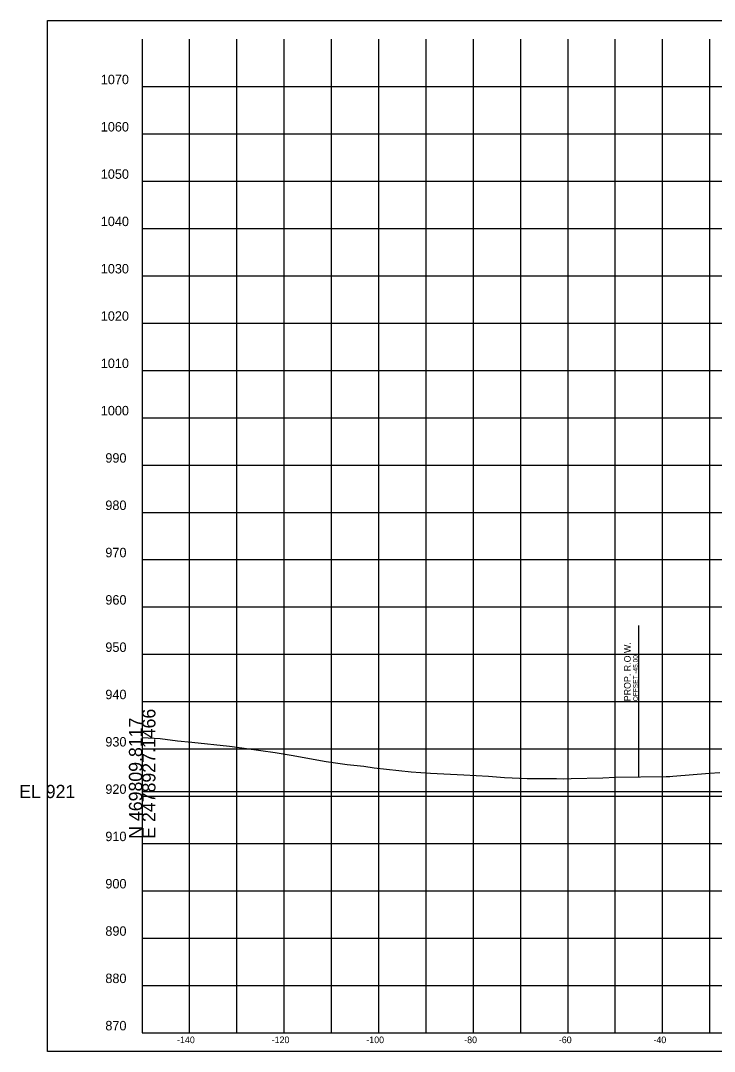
# Model space of a CAD drawing. Extents: x -26 to 2478923, y -10 to 469990.
# Drawn here: x -25.7 to 120.9, y 1945.1 to 2162.9 of the extents above; entities that cross this region are included whole.
import ezdxf

# ---------------------------------------------------------------- set-up
doc = ezdxf.new("R2010")
doc.units = 0
for name, color, linetype in [('DESIGN - ROW - Right-of-Way and Easement Labels', 7, 'Continuous'), ('DESIGN - ROW - Right-of-Way Linework', 7, 'Continuous'), ('DESIGN - SHEET - Corner Text', 7, 'Continuous'), ('DESIGN - SHEET - Light Grid', 7, 'Continuous'), ('DESIGN - SHEET - Linework', 7, 'Continuous'), ('DESIGN - SHEET - Plot Shape', 7, 'Continuous'), ('SURVEY - GROUND - Top of Ground', 7, 'Continuous')]:
    doc.layers.add(name, color=color, linetype=linetype)

msp = doc.modelspace()

# ---------------------------------------------------------------- linework, layer by layer
at = {"layer": 'DESIGN - ROW - Right-of-Way Linework'}
msp.add_line((105, 2003.07), (105, 2035.07), dxfattribs=at)
at = {"layer": 'DESIGN - SHEET - Light Grid'}
msp.add_line((0, 2000), (150, 2000), dxfattribs=at)
at = {"layer": 'DESIGN - SHEET - Linework'}
for p, q in [((10, 1949), (10, 2159)), ((10, 1949), (10, 2159)), ((10, 1949), (10, 2159)), ((10, 1949), (10, 2159)), ((20, 1949), (20, 2159)), ((20, 1949), (20, 2159)), ((20, 1949), (20, 2159)), ((20, 1949), (20, 2159)), ((30, 1949), (30, 2159)), ((30, 1949), (30, 2159)), ((30, 1949), (30, 2159)), ((30, 1949), (30, 2159)), ((40, 1949), (40, 2159)), ((40, 1949), (40, 2159)), ((40, 1949), (40, 2159)), ((40, 1949), (40, 2159)), ((50, 1949), (50, 2159)), ((50, 1949), (50, 2159)), ((50, 1949), (50, 2159)), ((50, 1949), (50, 2159)), ((60, 1949), (60, 2159)), ((60, 1949), (60, 2159)), ((60, 1949), (60, 2159)), ((60, 1949), (60, 2159)), ((70, 1949), (70, 2159)), ((70, 1949), (70, 2159)), ((70, 1949), (70, 2159)), ((70, 1949), (70, 2159)), ((80, 1949), (80, 2159)), ((80, 1949), (80, 2159)), ((80, 1949), (80, 2159)), ((80, 1949), (80, 2159)), ((90, 1949), (90, 2159)), ((90, 1949), (90, 2159)), ((90, 1949), (90, 2159)), ((90, 1949), (90, 2159)), ((100, 1949), (100, 2159)), ((100, 1949), (100, 2159)), ((100, 1949), (100, 2159)), ((100, 1949), (100, 2159)), ((110, 1949), (110, 2159)), ((110, 1949), (110, 2159)), ((110, 1949), (110, 2159)), ((110, 1949), (110, 2159)), ((120, 1949), (120, 2159)), ((120, 1949), (120, 2159)), ((120, 1949), (120, 2159)), ((120, 1949), (120, 2159)), ((0, 2149), (300, 2149)), ((0, 2149), (300, 2149)), ((0, 2149), (300, 2149)), ((0, 2149), (300, 2149)), ((0, 2139), (300, 2139)), ((0, 2139), (300, 2139)), ((0, 2139), (300, 2139)), ((0, 2139), (300, 2139)), ((0, 2129), (300, 2129)), ((0, 2129), (300, 2129)), ((0, 2129), (300, 2129)), ((0, 2129), (300, 2129)), ((0, 2119), (300, 2119)), ((0, 2119), (300, 2119)), ((0, 2119), (300, 2119)), ((0, 2119), (300, 2119)), ((0, 2109), (300, 2109)), ((0, 2109), (300, 2109)), ((0, 2109), (300, 2109)), ((0, 2109), (300, 2109)), ((0, 2099), (300, 2099)), ((0, 2099), (300, 2099)), ((0, 2099), (300, 2099)), ((0, 2099), (300, 2099)), ((0, 2089), (300, 2089)), ((0, 2089), (300, 2089)), ((0, 2089), (300, 2089)), ((0, 2089), (300, 2089)), ((0, 2079), (300, 2079)), ((0, 2079), (300, 2079)), ((0, 2079), (300, 2079)), ((0, 2079), (300, 2079)), ((0, 2069), (300, 2069)), ((0, 2069), (300, 2069)), ((0, 2069), (300, 2069)), ((0, 2069), (300, 2069)), ((0, 2059), (300, 2059)), ((0, 2059), (300, 2059)), ((0, 2059), (300, 2059)), ((0, 2059), (300, 2059)), ((0, 2049), (300, 2049)), ((0, 2049), (300, 2049)), ((0, 2049), (300, 2049)), ((0, 2049), (300, 2049)), ((0, 2039), (300, 2039)), ((0, 2039), (300, 2039)), ((0, 2039), (300, 2039)), ((0, 2039), (300, 2039)), ((0, 2029), (300, 2029)), ((0, 2029), (300, 2029)), ((0, 2029), (300, 2029)), ((0, 2029), (300, 2029)), ((0, 2019), (300, 2019)), ((0, 2019), (300, 2019)), ((0, 2019), (300, 2019)), ((0, 2019), (300, 2019)), ((0, 2009), (300, 2009)), ((0, 2009), (300, 2009)), ((0, 2009), (300, 2009)), ((0, 2009), (300, 2009)), ((0, 1999), (300, 1999)), ((0, 1999), (300, 1999)), ((0, 1999), (300, 1999)), ((0, 1999), (300, 1999)), ((0, 1989), (300, 1989)), ((0, 1989), (300, 1989)), ((0, 1989), (300, 1989)), ((0, 1989), (300, 1989)), ((0, 1979), (300, 1979)), ((0, 1979), (300, 1979)), ((0, 1979), (300, 1979)), ((0, 1979), (300, 1979)), ((0, 1969), (300, 1969)), ((0, 1969), (300, 1969)), ((0, 1969), (300, 1969)), ((0, 1969), (300, 1969)), ((0, 1959), (300, 1959)), ((0, 1959), (300, 1959)), ((0, 1959), (300, 1959)), ((0, 1959), (300, 1959))]:
    msp.add_line(p, q, dxfattribs=at)
msp.add_lwpolyline([(0, 2159), (0, 1949), (300, 1949), (300, 2159)], dxfattribs=at)
msp.add_lwpolyline([(0, 2159), (0, 1949), (300, 1949), (300, 2159)], dxfattribs=at)
msp.add_lwpolyline([(0, 2159), (0, 1949), (300, 1949), (300, 2159)], dxfattribs=at)
msp.add_lwpolyline([(0, 2159), (0, 1949), (300, 1949), (300, 2159)], dxfattribs=at)
at = {"layer": 'DESIGN - SHEET - Plot Shape'}
msp.add_lwpolyline([(-20, 2162.94), (320, 2162.94), (320, 1945.06), (-20, 1945.06)], close=True, dxfattribs=at)
msp.add_lwpolyline([(-20, 2162.94), (320, 2162.94), (320, 1945.06), (-20, 1945.06)], close=True, dxfattribs=at)
msp.add_lwpolyline([(-20, 2162.94), (320, 2162.94), (320, 1945.06), (-20, 1945.06)], close=True, dxfattribs=at)
msp.add_lwpolyline([(-20, 2162.94), (320, 2162.94), (320, 1945.06), (-20, 1945.06)], close=True, dxfattribs=at)
at = {"layer": 'SURVEY - GROUND - Top of Ground'}
msp.add_lwpolyline([(0, 2011.39), (3.83, 2011.2), (7.48, 2010.68), (10.51, 2010.41), (18.47, 2009.59), (19.05, 2009.53), (28.13, 2008.21), (31.5, 2007.67), (38.89, 2006.31), (40.85, 2006.05), (43.3, 2005.72), (46.82, 2005.34), (49.04, 2005.02), (56.85, 2004.15), (60.91, 2003.9), (68.01, 2003.51), (73.19, 2003.24), (76.56, 2002.98), (81.37, 2002.72), (87.57, 2002.73), (89.01, 2002.69), (90.67, 2002.72), (97.33, 2002.87), (99.95, 2002.99), (110.77, 2003.16), (111.53, 2003.18), (112.18, 2003.22), (119.89, 2003.88), (122.1, 2004)], dxfattribs=at)

# ---------------------------------------------------------------- texts
at = {"layer": 'DESIGN - ROW - Right-of-Way and Easement Labels'}
for s, height, p in [('PROP. R.O.W.', 1.4, (103.25, 2019.07)), ('OFFSET -45.00', 1, (104.75, 2019.07))]:
    msp.add_text(s, height=height, rotation=90, dxfattribs=at).set_placement(p)
at = {"layer": 'DESIGN - SHEET - Corner Text'}
for s, height, p in [('1070', 2, (-8.75, 2149.5)), ('1070', 2, (-8.75, 2149.5)), ('1070', 2, (-8.75, 2149.5)), ('1070', 2, (-8.75, 2149.5)), ('1060', 2, (-8.75, 2139.5)), ('1060', 2, (-8.75, 2139.5)), ('1060', 2, (-8.75, 2139.5)), ('1060', 2, (-8.75, 2139.5)), ('1050', 2, (-8.75, 2129.5)), ('1050', 2, (-8.75, 2129.5)), ('1050', 2, (-8.75, 2129.5)), ('1050', 2, (-8.75, 2129.5)), ('1040', 2, (-8.75, 2119.5)), ('1040', 2, (-8.75, 2119.5)), ('1040', 2, (-8.75, 2119.5)), ('1040', 2, (-8.75, 2119.5)), ('1030', 2, (-8.75, 2109.5)), ('1030', 2, (-8.75, 2109.5)), ('1030', 2, (-8.75, 2109.5)), ('1030', 2, (-8.75, 2109.5)), ('1020', 2, (-8.75, 2099.5)), ('1020', 2, (-8.75, 2099.5)), ('1020', 2, (-8.75, 2099.5)), ('1020', 2, (-8.75, 2099.5)), ('1010', 2, (-8.75, 2089.5)), ('1010', 2, (-8.75, 2089.5)), ('1010', 2, (-8.75, 2089.5)), ('1010', 2, (-8.75, 2089.5)), ('1000', 2, (-8.75, 2079.5)), ('1000', 2, (-8.75, 2079.5)), ('1000', 2, (-8.75, 2079.5)), ('1000', 2, (-8.75, 2079.5)), ('990', 2, (-7.78, 2069.5)), ('990', 2, (-7.78, 2069.5)), ('990', 2, (-7.78, 2069.5)), ('990', 2, (-7.78, 2069.5)), ('980', 2, (-7.78, 2059.5)), ('980', 2, (-7.78, 2059.5)), ('980', 2, (-7.78, 2059.5)), ('980', 2, (-7.78, 2059.5)), ('970', 2, (-7.78, 2049.5)), ('970', 2, (-7.78, 2049.5)), ('970', 2, (-7.78, 2049.5)), ('970', 2, (-7.78, 2049.5)), ('960', 2, (-7.78, 2039.5)), ('960', 2, (-7.78, 2039.5)), ('960', 2, (-7.78, 2039.5)), ('960', 2, (-7.78, 2039.5)), ('950', 2, (-7.78, 2029.5)), ('950', 2, (-7.78, 2029.5)), ('950', 2, (-7.78, 2029.5)), ('950', 2, (-7.78, 2029.5)), ('940', 2, (-7.78, 2019.5)), ('940', 2, (-7.78, 2019.5)), ('940', 2, (-7.78, 2019.5)), ('940', 2, (-7.78, 2019.5)), ('930', 2, (-7.78, 2009.5)), ('930', 2, (-7.78, 2009.5)), ('930', 2, (-7.78, 2009.5)), ('930', 2, (-7.78, 2009.5)), ('920', 2, (-7.78, 1999.5)), ('920', 2, (-7.78, 1999.5)), ('920', 2, (-7.78, 1999.5)), ('920', 2, (-7.78, 1999.5)), ('910', 2, (-7.78, 1989.5)), ('910', 2, (-7.78, 1989.5)), ('910', 2, (-7.78, 1989.5)), ('910', 2, (-7.78, 1989.5)), ('900', 2, (-7.78, 1979.5)), ('900', 2, (-7.78, 1979.5)), ('900', 2, (-7.78, 1979.5)), ('900', 2, (-7.78, 1979.5)), ('890', 2, (-7.78, 1969.5)), ('890', 2, (-7.78, 1969.5)), ('890', 2, (-7.78, 1969.5)), ('890', 2, (-7.78, 1969.5)), ('880', 2, (-7.78, 1959.5)), ('880', 2, (-7.78, 1959.5)), ('880', 2, (-7.78, 1959.5)), ('880', 2, (-7.78, 1959.5)), ('870', 2, (-7.78, 1949.5)), ('870', 2, (-7.78, 1949.5)), ('870', 2, (-7.78, 1949.5)), ('870', 2, (-7.78, 1949.5)), ('-140', 1.4, (7.37, 1946.8)), ('-140', 1.4, (7.37, 1946.8)), ('-140', 1.4, (7.37, 1946.8)), ('-140', 1.4, (7.37, 1946.8)), ('-120', 1.4, (27.37, 1946.8)), ('-120', 1.4, (27.37, 1946.8)), ('-120', 1.4, (27.37, 1946.8)), ('-120', 1.4, (27.37, 1946.8)), ('-100', 1.4, (47.37, 1946.8)), ('-100', 1.4, (47.37, 1946.8)), ('-100', 1.4, (47.37, 1946.8)), ('-100', 1.4, (47.37, 1946.8)), ('-80', 1.4, (68.06, 1946.8)), ('-80', 1.4, (68.06, 1946.8)), ('-80', 1.4, (68.06, 1946.8)), ('-80', 1.4, (68.06, 1946.8)), ('-60', 1.4, (88.06, 1946.8)), ('-60', 1.4, (88.06, 1946.8)), ('-60', 1.4, (88.06, 1946.8)), ('-60', 1.4, (88.06, 1946.8)), ('-40', 1.4, (108.06, 1946.8)), ('-40', 1.4, (108.06, 1946.8)), ('-40', 1.4, (108.06, 1946.8)), ('-40', 1.4, (108.06, 1946.8))]:
    msp.add_text(s, height=height, dxfattribs=at).set_placement(p)
at = {"layer": 'DESIGN - SHEET - Light Grid'}
for s, p in [('N 469809.8117', (0, 1990)), ('E 2478927.1466', (2.8, 1990))]:
    msp.add_text(s, height=2.8, rotation=90, dxfattribs=at).set_placement(p)
msp.add_text('EL 921', height=2.8, dxfattribs=at).set_placement((-26, 1998.6))

doc.saveas('drawing.dxf')
